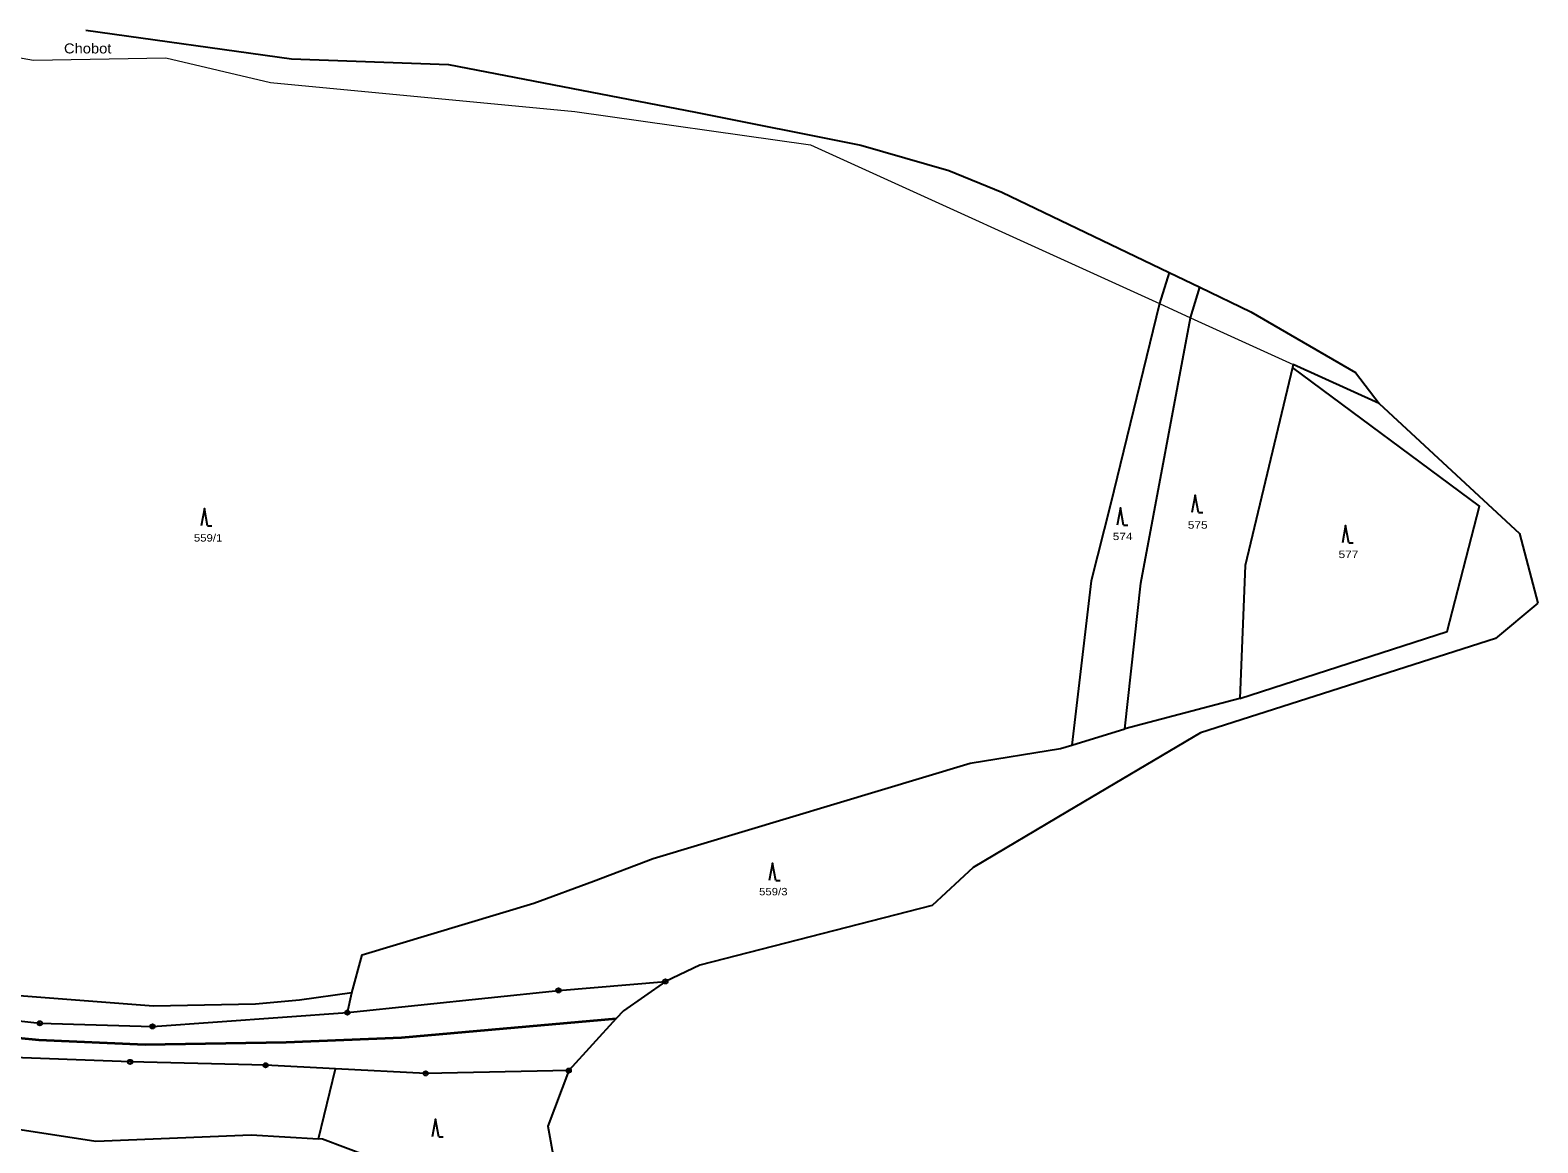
# Model space of a CAD drawing. Extents: x -872229 to -869198, y -1075981 to -1074329.
# Drawn here: x -869544.7 to -869197.7, y -1075466.2 to -1075210.2 of the extents above; entities that cross this region are included whole.
import ezdxf
from ezdxf.enums import TextEntityAlignment as Align

# ---------------------------------------------------------------- set-up
doc = ezdxf.new("R2010")
doc.units = 0
doc.header["$LTSCALE"] = 0.68
for name, color, linetype, lineweight in [('1', 7, 'Continuous', 25), ('3', 7, 'Continuous', 25), ('4', 7, 'Continuous', 13), ('6', 7, 'Continuous', 25), ('7', 7, 'Continuous', 13), ('8', 7, 'Continuous', 25)]:
    doc.layers.add(name, color=color, linetype=linetype, lineweight=lineweight)
doc.layers.add('2', color=7, linetype='Continuous')

msp = doc.modelspace()

# ---------------------------------------------------------------- linework, layer by layer
at = {"layer": '1'}
for p, q in [((-869266.25, -1075363.99), (-869292.73, -1075370.98)), ((-869398.45, -1075429.07), (-869408.14, -1075435.84)), ((-869478.29, -1075465.32), (-869474.41, -1075449.19))]:
    msp.add_line(p, q, dxfattribs=at)
for points in [[(-869531.81, -1075210.17), (-869484.54, -1075216.74), (-869448.42, -1075218.1), (-869391.54, -1075229.06)], [(-869391.54, -1075229.06), (-869353.52, -1075236.64), (-869333.23, -1075242.46), (-869321.07, -1075247.48), (-869282.53, -1075265.95), (-869275.45, -1075269.34)], [(-869282.53, -1075265.95), (-869284.79, -1075273.08), (-869296.06, -1075319.3), (-869300.48, -1075336.87), (-869304.9, -1075374.68), (-869292.73, -1075370.98)], [(-869292.73, -1075370.98), (-869289.05, -1075337.45), (-869277.59, -1075276.36), (-869275.45, -1075269.34)], [(-869275.45, -1075269.34), (-869263.72, -1075274.96), (-869239.64, -1075288.97), (-869234.22, -1075296.09), (-869201.89, -1075326.03), (-869197.69, -1075342.02)], [(-869266.25, -1075363.99), (-869218.58, -1075348.55), (-869211.15, -1075319.68), (-869254.14, -1075287.83)], [(-869254.14, -1075287.83), (-869265.05, -1075333.33), (-869266.25, -1075363.99)], [(-869234.22, -1075296.09), (-869253.97, -1075287.1), (-869254.14, -1075287.83)], [(-869197.69, -1075342.02), (-869207.41, -1075350.18), (-869275.36, -1075371.88), (-869305.91, -1075389.99), (-869327.65, -1075402.88), (-869337.06, -1075411.58)], [(-869470.63, -1075431.72), (-869468.23, -1075422.93), (-869428.75, -1075411.1), (-869415.02, -1075406.03), (-869401.31, -1075400.81), (-869328.31, -1075378.82), (-869307.57, -1075375.49), (-869304.9, -1075374.68)], [(-869470.63, -1075431.72), (-869482.67, -1075433.38), (-869492.77, -1075434.3), (-869516.25, -1075434.78), (-869548.16, -1075432.33), (-869575.31, -1075429.18), (-869592.79, -1075426.68), (-869627.42, -1075419.15), (-869656.02, -1075410.53), (-869671.66, -1075407.34), (-869676.3, -1075404.74)], [(-869682.1, -1075410.63), (-869678.59, -1075410.32), (-869671.56, -1075413.43), (-869624.66, -1075426.43), (-869585.55, -1075433.9), (-869542.43, -1075438.72), (-869516.5, -1075439.44), (-869471.65, -1075436.24), (-869470.63, -1075431.72)], [(-869337.06, -1075411.58), (-869390.53, -1075425.32), (-869398.45, -1075429.07)], [(-869474.41, -1075449.19), (-869490.49, -1075448.38), (-869521.65, -1075447.59), (-869552.7, -1075446.43), (-869583.47, -1075442.4), (-869614.13, -1075437.41), (-869643.97, -1075429.64), (-869680.93, -1075420.53), (-869682.99, -1075432.01), (-869660.1, -1075439.54)], [(-869471.65, -1075436.24), (-869423.07, -1075431.15), (-869398.45, -1075429.07)], [(-869408.14, -1075435.84), (-869409.77, -1075437.63), (-869420.7, -1075449.61)], [(-869660.1, -1075439.54), (-869639.17, -1075443.87), (-869615.03, -1075449.51), (-869552.02, -1075462.41), (-869529.57, -1075465.84), (-869493.81, -1075464.4), (-869478.29, -1075465.32)], [(-869420.7, -1075449.61), (-869453.61, -1075450.25), (-869474.41, -1075449.19)], [(-869420.7, -1075449.61), (-869425.54, -1075462.39), (-869421.29, -1075485.67)], [(-869421.29, -1075485.67), (-869434.21, -1075480.71), (-869445.65, -1075477.37), (-869477.35, -1075465.38), (-869478.29, -1075465.32)]]:
    msp.add_lwpolyline(points, dxfattribs=at)
at = {"layer": '3'}
for p, q in [((-869503.82, -1075324.24), (-869502.824, -1075324.24)), ((-869293.02, -1075324.12), (-869292.024, -1075324.12)), ((-869275.8, -1075321.15), (-869274.804, -1075321.15)), ((-869241.17, -1075328.18), (-869240.174, -1075328.18)), ((-869373.08, -1075405.88), (-869372.084, -1075405.88)), ((-869450.63, -1075464.81), (-869449.634, -1075464.81))]:
    msp.add_line(p, q, dxfattribs=at)
for points in [[(-869275.8, -1075321.15), (-869276.55, -1075317.15), (-869277.3, -1075321.15)], [(-869503.82, -1075324.24), (-869504.57, -1075320.24), (-869505.32, -1075324.24)], [(-869293.02, -1075324.12), (-869293.77, -1075320.12), (-869294.52, -1075324.12)], [(-869241.17, -1075328.18), (-869241.92, -1075324.18), (-869242.67, -1075328.18)], [(-869373.08, -1075405.88), (-869373.83, -1075401.88), (-869374.58, -1075405.88)], [(-869450.63, -1075464.81), (-869451.38, -1075460.81), (-869452.13, -1075464.81)]]:
    msp.add_lwpolyline(points, dxfattribs=at)
at = {"layer": '4'}
msp.add_line((-869583.06, -1075210.18), (-869543.86, -1075217.07), dxfattribs=at)
msp.add_lwpolyline([(-869543.86, -1075217.07), (-869513.42, -1075216.57), (-869489.36, -1075222.2), (-869419.31, -1075228.93), (-869365.07, -1075236.56), (-869284.79, -1075273.08), (-869277.59, -1075276.36), (-869253.97, -1075287.1)], dxfattribs=at)
at = {"layer": '6', "lineweight": 35}
msp.add_lwpolyline([(-869860.88, -1075365.74), (-869846.01, -1075369.94), (-869704.43, -1075408.78), (-869641.66, -1075426.07), (-869625.84, -1075430.18), (-869607.72, -1075434.15), (-869580.2, -1075438.82), (-869542.66, -1075442.5), (-869518.18, -1075443.57), (-869485.71, -1075443.04), (-869459.17, -1075441.98), (-869409.77, -1075437.63)], dxfattribs=at)
at = {"layer": '8'}
for centre, radius in [((-869398.45, -1075429.0699), 0.5), ((-869423.07, -1075431.1499), 0.5), ((-869423.07, -1075431.1499), 0.0303), ((-869398.45, -1075429.0699), 0.0303), ((-869542.43, -1075438.7199), 0.5), ((-869542.43, -1075438.7199), 0.0303), ((-869516.5, -1075439.4399), 0.5), ((-869471.65, -1075436.2399), 0.5), ((-869471.65, -1075436.2399), 0.0303), ((-869516.5, -1075439.4399), 0.0303), ((-869521.65, -1075447.5899), 0.5), ((-869521.65, -1075447.5899), 0.0303), ((-869490.49, -1075448.3799), 0.5), ((-869490.49, -1075448.3799), 0.0303), ((-869420.7, -1075449.6099), 0.5), ((-869453.61, -1075450.2499), 0.5), ((-869453.61, -1075450.2499), 0.0303), ((-869420.7, -1075449.6099), 0.0303)]:
    msp.add_circle(centre, radius, dxfattribs=at)

# ---------------------------------------------------------------- texts
at = {"layer": '2'}
for s, width, p in [('575', 1.2, (-869278.24, -1075324.9)), ('559/1', 1.15, (-869506.98, -1075327.86)), ('574', 1.2, (-869295.52, -1075327.52)), ('577', 1.2, (-869243.55, -1075331.66)), ('559/3', 1.15, (-869376.91, -1075409.26))]:
    msp.add_text(s, height=1.7, dxfattribs=dict(at, width=width)).set_placement(p)
at = {"layer": '7', "width": 1.1}
msp.add_text('Chobot', height=2.3, dxfattribs=at).set_placement((-869531.42, -1075215.53), align=Align.CENTER)

doc.saveas('drawing.dxf')
